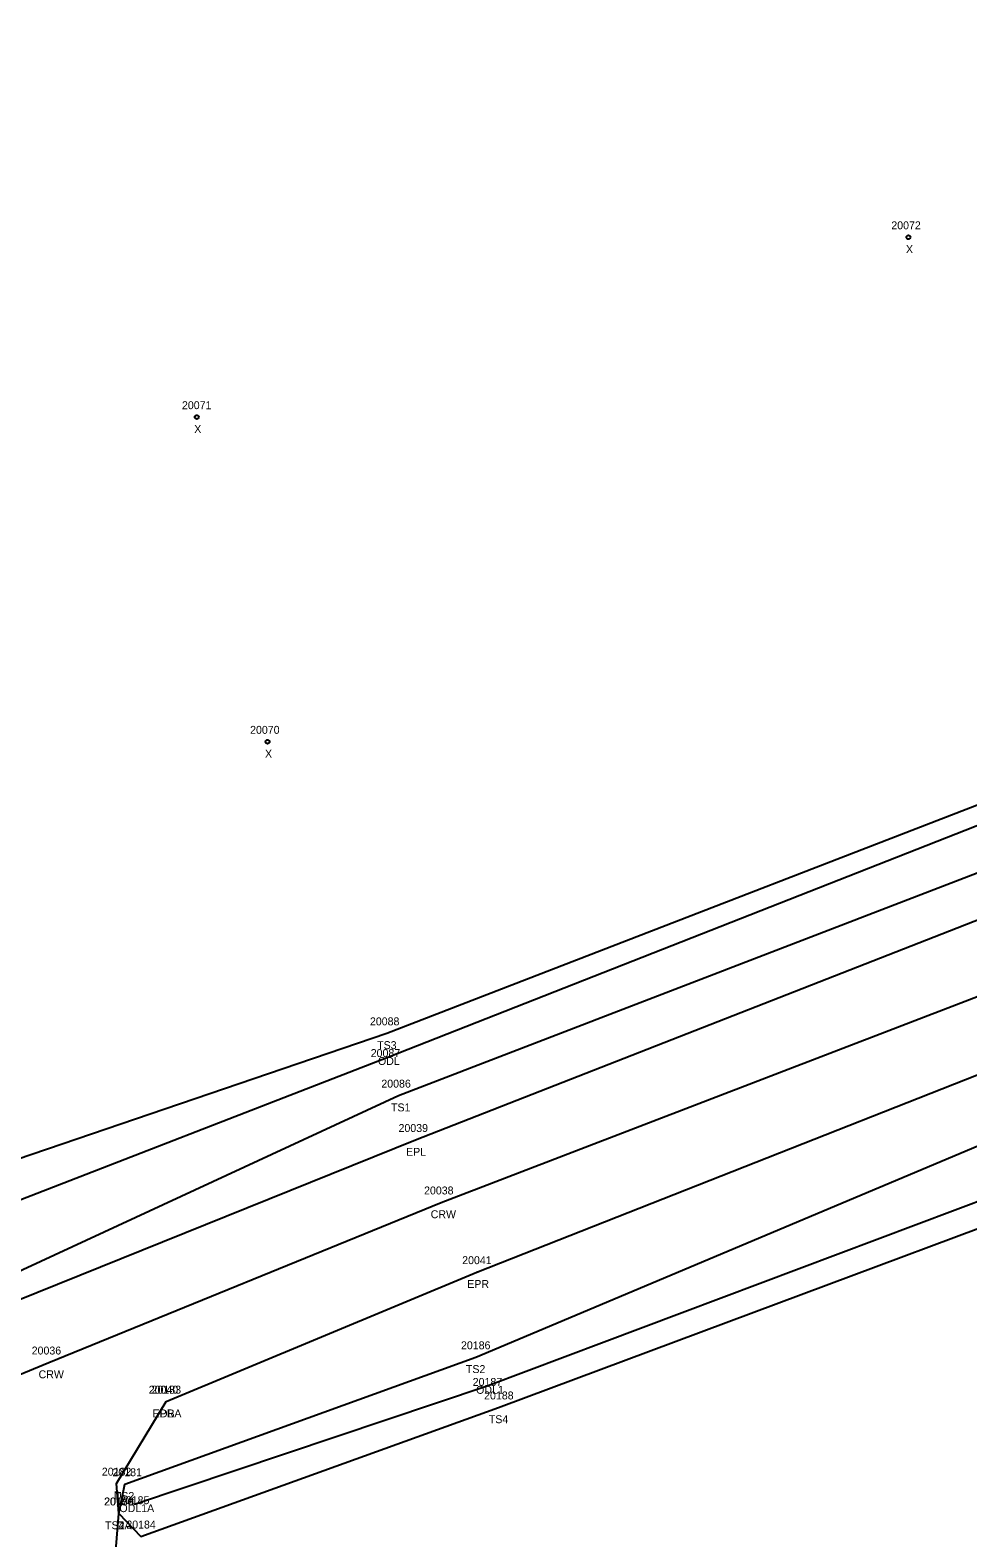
# Model space of a CAD drawing. Extents: x 1966740 to 1969291, y 1117378 to 1118461.
# Drawn here: x 1967322.9 to 1967441.2, y 1117652.7 to 1117842.9 of the extents above; entities that cross this region are included whole.
import ezdxf

# ---------------------------------------------------------------- set-up
doc = ezdxf.new("R2010")
doc.units = 0
for name, color, linetype in [('RD_DTM_BkLn1', 7, 'Continuous'), ('RD_DTM_BkLn2', 7, 'Continuous'), ('RD_EX_Driveway', 7, 'Continuous'), ('RD_EX_Driveway_txCode', 7, 'Continuous'), ('RD_EX_H2O', 7, 'Continuous'), ('RD_EX_H2O_txCode', 7, 'Continuous'), ('RD_EX_Road', 7, 'Continuous'), ('RD_EX_Road_txCode', 7, 'Continuous'), ('RD_SMD_Locator', 7, 'Continuous'), ('RD_SMD_Misc', 7, 'Continuous')]:
    doc.layers.add(name, color=color, linetype=linetype)

msp = doc.modelspace()

# ---------------------------------------------------------------- linework, layer by layer
at = {"layer": 'RD_DTM_BkLn1'}
msp.add_lwpolyline([(1966772.57, 1117449.88), (1966874.49, 1117489.87), (1966974.64, 1117529.93), (1967075.06, 1117571.68), (1967175.91, 1117613.34), (1967274.11, 1117653.69), (1967325.25, 1117674.8), (1967374.73, 1117695), (1967473.9, 1117733.1), (1967569.8, 1117771.9), (1967665.19, 1117809.79), (1967697.89, 1117822.8)], dxfattribs=at)
at = {"layer": 'RD_DTM_BkLn2'}
for points in [[(1966768.15, 1117461.43), (1966869.41, 1117499.34), (1967070.52, 1117582.35), (1967171.25, 1117624.02), (1967269.74, 1117664.9), (1967320.21, 1117685.71), (1967369.37, 1117708.48), (1967468.51, 1117746.66), (1967564.6, 1117784.47), (1967654.68, 1117828.05), (1967680.1, 1117841.48), (1967687.91, 1117842.93), (1967691.45, 1117838.71), (1967693.03, 1117834.22)], [(1967334.06, 1117655.75), (1967334.81, 1117659.44), (1967379.1, 1117675.46), (1967480.83, 1117718.27), (1967577.81, 1117756.42), (1967702.07, 1117801.85), (1967703.17, 1117805.75), (1967702.89, 1117809.87)], [(1966766.42, 1117472.19), (1966865.47, 1117508.82), (1967066.64, 1117593.45), (1967166.55, 1117636.11), (1967264.62, 1117677.56), (1967315.66, 1117698.57), (1967367.9, 1117716.34), (1967464.92, 1117753.87), (1967560.73, 1117793.63)], [(1967334.06, 1117655.75), (1967336.84, 1117652.84), (1967381.99, 1117669.13), (1967487.42, 1117708.48)]]:
    msp.add_lwpolyline(points, dxfattribs=at)
at = {"layer": 'RD_EX_Driveway'}
msp.add_lwpolyline([(1967289.71, 1117583.09), (1967289.16, 1117587.89), (1967295.61, 1117597.52), (1967308.21, 1117610.4), (1967325.87, 1117628.48), (1967333.04, 1117643.27), (1967334.06, 1117655.75), (1967333.75, 1117659.51), (1967340.03, 1117669.86)], dxfattribs=at)
at = {"layer": 'RD_EX_H2O'}
for points in [[(1966766.64, 1117466.58), (1966867.24, 1117504.5), (1967068.76, 1117586.41), (1967167.95, 1117632.67), (1967266.82, 1117671.88), (1967316.79, 1117693.47), (1967368.01, 1117713.34), (1967465.67, 1117751.74), (1967560.73, 1117793.63)], [(1967336.04, 1117656.91), (1967380.56, 1117671.84), (1967483.89, 1117710.7), (1967580.8, 1117748.62), (1967673.4, 1117777.22)]]:
    msp.add_lwpolyline(points, dxfattribs=at)
at = {"layer": 'RD_EX_Road'}
for points in [[(1966769.51, 1117457.48), (1966870.16, 1117497.34), (1966971.19, 1117538.95), (1967071.09, 1117580.24), (1967172.6, 1117621.53), (1967270.79, 1117661.66), (1967321.12, 1117682.57), (1967371.52, 1117702.88), (1967470.26, 1117741.55), (1967566.67, 1117779.5), (1967661.25, 1117817.53), (1967694.4, 1117831.19), (1967697.89, 1117822.8)], [(1967340.03, 1117669.86), (1967379.26, 1117686.2), (1967476.09, 1117724.39), (1967573.92, 1117763.51), (1967667.7, 1117800.74), (1967701.64, 1117814), (1967697.89, 1117822.8)]]:
    msp.add_lwpolyline(points, dxfattribs=at)
at = {"layer": 'RD_SMD_Locator'}
for centre, radius in [((1967433.7, 1117816.8), 0.25), ((1967343.9, 1117794.1), 0.25), ((1967352.83, 1117753.13), 0.25), ((1967367.9, 1117716.34), 0.001), ((1967368.01, 1117713.34), 0.001), ((1967369.37, 1117708.48), 0.001), ((1967371.52, 1117702.88), 0.001), ((1967374.73, 1117695), 0.001), ((1967379.26, 1117686.2), 0.001), ((1967325.25, 1117674.8), 0.001), ((1967379.1, 1117675.46), 0.001), ((1967380.56, 1117671.84), 0.001), ((1967340.03, 1117669.86), 0.001), ((1967340.03, 1117669.86), 0.001), ((1967381.99, 1117669.13), 0.001), ((1967333.75, 1117659.51), 0.001), ((1967334.81, 1117659.44), 0.001), ((1967336.04, 1117656.91), 0.001), ((1967334.06, 1117655.75), 0.001), ((1967334.06, 1117655.75), 0.001), ((1967334.06, 1117655.75), 0.001), ((1967336.84, 1117652.84), 0.001)]:
    msp.add_circle(centre, radius, dxfattribs=at)

# ---------------------------------------------------------------- texts
at = {"layer": 'RD_EX_Driveway_txCode'}
for s, p in [('20183', (1967338.2, 1117670.86)), ('DB', (1967339.25, 1117667.86)), ('20182', (1967331.92, 1117660.51)), ('20178', (1967332.23, 1117656.75)), ('D', (1967333.45, 1117657.51)), ('D', (1967333.76, 1117653.75))]:
    msp.add_text(s, height=1, dxfattribs=at).set_placement(p)
at = {"layer": 'RD_EX_H2O_txCode'}
for s, p in [('20087', (1967365.85, 1117713.34)), ('ODL', (1967366.76, 1117712.34)), ('20187', (1967378.72, 1117671.84)), ('ODL1', (1967379.15, 1117670.84)), ('ODL1A', (1967334.14, 1117655.91)), ('20185', (1967334.2, 1117656.91))]:
    msp.add_text(s, height=1, dxfattribs=at).set_placement(p)
at = {"layer": 'RD_EX_Road_txCode'}
for s, p in [('20039', (1967369.36, 1117703.88)), ('EPL', (1967370.31, 1117700.88)), ('20041', (1967377.39, 1117687.2)), ('EPR', (1967378.03, 1117684.2)), ('20040', (1967337.84, 1117670.86)), ('EPRA', (1967338.32, 1117667.86))]:
    msp.add_text(s, height=1, dxfattribs=at).set_placement(p)
at = {"layer": 'RD_SMD_Misc'}
for s, p in [('20072', (1967431.54, 1117817.8)), ('X', (1967433.39, 1117814.8)), ('20071', (1967342.03, 1117795.1)), ('X', (1967343.58, 1117792.1)), ('20070', (1967350.63, 1117754.13)), ('X', (1967352.51, 1117751.13)), ('20088', (1967365.75, 1117717.34)), ('TS3', (1967366.66, 1117714.34)), ('20086', (1967367.19, 1117709.48)), ('TS1', (1967368.41, 1117706.48)), ('20038', (1967372.58, 1117696)), ('CRW', (1967373.42, 1117693)), ('20036', (1967323.07, 1117675.8)), ('20186', (1967377.24, 1117676.46)), ('CRW', (1967323.94, 1117672.8)), ('TS2', (1967377.86, 1117673.46)), ('20188', (1967380.16, 1117670.13)), ('TS4', (1967380.75, 1117667.13)), ('20181', (1967333.26, 1117660.44)), ('20180', (1967332.19, 1117656.75)), ('20179', (1967332.23, 1117656.75)), ('TS2', (1967333.56, 1117657.44)), ('20184', (1967335.01, 1117653.84)), ('TS2A', (1967332.33, 1117653.75)), ('TS4A', (1967332.33, 1117653.75))]:
    msp.add_text(s, height=1, dxfattribs=at).set_placement(p)

doc.saveas('drawing.dxf')
